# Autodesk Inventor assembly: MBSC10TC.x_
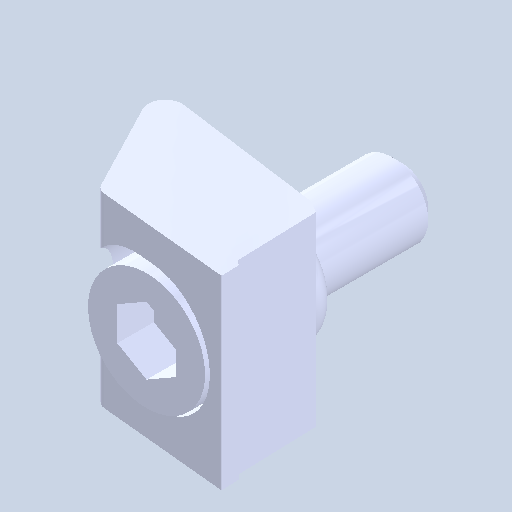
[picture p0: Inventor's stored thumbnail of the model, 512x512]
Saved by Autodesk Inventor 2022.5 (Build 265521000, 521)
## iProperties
Created: 2024-05
Part Number: MBSC10TC.x_
Document SubType Name: Assembly
Designer: ImaoCorp
Author: ImaoCorp
Sending System: SOLIDWORKS 2022-2022290
MC: AMD64
MC_MODEL: Intel64 Family 6 Model 60 Stepping 3, GenuineIntel
OS: Windows_NT
FRU: Parasolid Version 33.1, build 260,  4-25-2022
FORMAT: text
GUISE: transmit
KEY: FILEMBSC10TC.x_t
DATE: Mon May 20 16:28:05 2024
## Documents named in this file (4)
- X:\14_SW2022-Inv2022\保留中\mitee-bite\データ\mbsc10tc\MBSC10TC.x_.iam
- X:\14_SW2022-Inv2022\保留中\mitee-bite\データ\mbsc10tc\MBSC10TC_01.ipt
- X:\14_SW2022-Inv2022\保留中\mitee-bite\データ\mbsc10tc\MBSC10TC_02.ipt
- X:\14_SW2022-Inv2022\保留中\mitee-bite\データ\mbsc10tc\MBSC10TC_03.ipt
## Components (3 placed, 3 different names)
1. MBSC10TC_01
2. MBSC10TC_02
3. MBSC10TC_03
